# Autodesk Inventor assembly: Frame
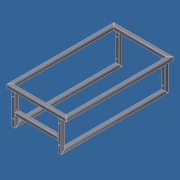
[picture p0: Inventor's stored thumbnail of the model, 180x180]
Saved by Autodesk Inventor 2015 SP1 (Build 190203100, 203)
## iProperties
Created: 2011-06
Part Number: Frame
Document SubType Name: Weldment
Designer: Guilherme Augusto Franco de Souza
Engineer: George Geraldo de Oliveia Silva
Authority: Fábio Ricardo de Oliveira Soza
Weld Material: Welded Stainless Steel, 440C
Description: Sub-assembly
_SolveAssemblyDoc: Frame Generator Solve Assembly
_Version: 15.0.0
Category: Mechanical Engineering Drawing and Design - CADD
Manager: Fábio Ricardo de Oliveira Souza
Company: SENAI - Serviço Nacional de Aprendizagem Industrial
Subject: WorldSkill 2011 - London, England
Author: Guilherme Augusto Franco de Souza
Revision Number: 00
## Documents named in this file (3)
- E:\Visitor Experience Project\WSI2015 - Visitor Experience Project\#46- Sheet Metal Technology\01- 3D Models\Outodoor Heater\2- Assemblies\Frame.iam
- E:\Visitor Experience Project\WSI2015 - Visitor Experience Project\#46- Sheet Metal Technology\01- 3D Models\Outodoor Heater\1- Parts\Skeleton.ipt
- E:\Visitor Experience Project\WSI2015 - Visitor Experience Project\#46- Sheet Metal Technology\01- 3D Models\Outodoor Heater\2- Assemblies\Frame\Frame\Frame0001.iam
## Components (2 placed, 2 different names)
1. Skeleton:1
2. Frame0001:1 [sub-assembly]
